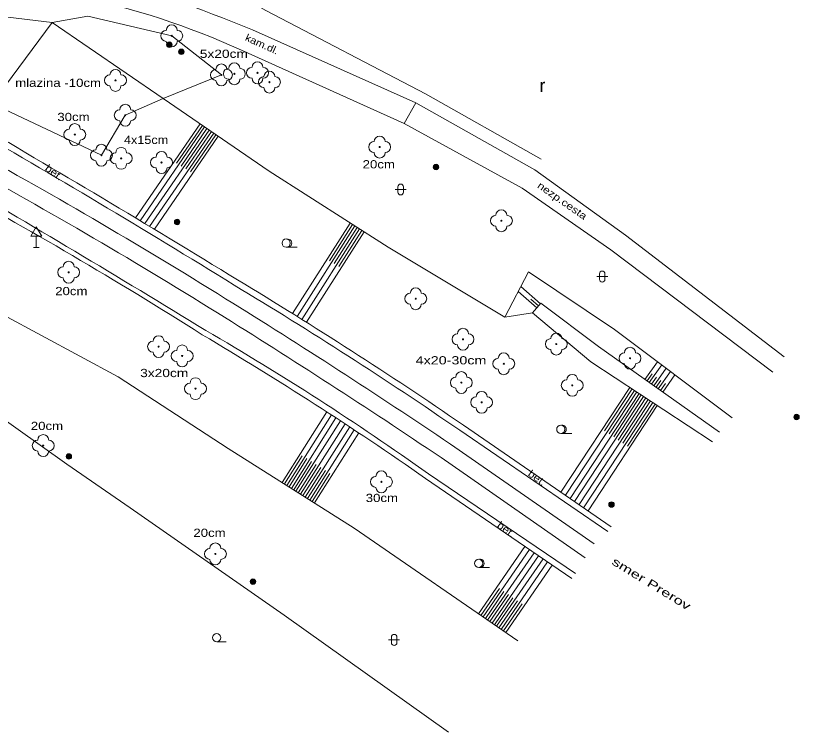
# Model space of a CAD drawing. Extents: x -568501 to -568291, y -1154101 to -1153799.
# Drawn here: x -568402 to -568330.5, y -1153981.7 to -1153916.3 of the extents above; entities that cross this region are included whole.
import ezdxf
from ezdxf.enums import TextEntityAlignment as Align

# ---------------------------------------------------------------- set-up
doc = ezdxf.new("R2010")
doc.units = 0
doc.header["$LTSCALE"] = 0.3
for name, color, linetype, lineweight in [('11', 7, 'Continuous', 13), ('12', 7, 'Continuous', 13), ('14', 7, 'Continuous', 13), ('15', 7, 'Continuous', 13), ('22', 7, 'Continuous', 13), ('23', 7, 'Continuous', 13), ('25', 7, 'Continuous', 13), ('34', 7, 'Continuous', 13), ('36', 7, 'Continuous', 13), ('42', 7, 'Continuous', 13), ('7', 7, 'Continuous', 13)]:
    doc.layers.add(name, color=color, linetype=linetype, lineweight=lineweight)
doc.layers.add('40', color=7, linetype='Continuous')

msp = doc.modelspace()

# ---------------------------------------------------------------- linework, layer by layer
at = {"layer": '11'}
for p, q in [((-568381.39, -1153919.46), (-568366.54, -1153926.14)), ((-568331.89, -1153947.44), (-568346.35, -1153936.33)), ((-568347.69, -1153937.68), (-568332.93, -1153948.84)), ((-568361.48, -1153954.12), (-568347.97, -1153963.37)), ((-568347.67, -1153962.92), (-568361.14, -1153953.66)), ((-568350.92, -1153967.19), (-568364.32, -1153958.11)), ((-568364.59, -1153958.52), (-568351.25, -1153967.65))]:
    msp.add_line(p, q, dxfattribs=at)
for points in [[(-568346.35, -1153936.33), (-568354.63, -1153930.38), (-568365.47, -1153924.26), (-568380.39, -1153917.61)], [(-568365.47, -1153924.26), (-568366.54, -1153926.14), (-568355.77, -1153932.04), (-568347.69, -1153937.68)]]:
    msp.add_lwpolyline(points, dxfattribs=at)
for centre, radius, start, end in [((-568450.7473, -1154089.926), 186.1261, 67.78962, 72.60711), ((-568410.9033, -1153984.3733), 71.3076, 65.55079, 78.28935), ((-569009.5906, -1154964.079), 1200.8724, 58.47781, 59.85365), ((-568847.5367, -1154693.8111), 885.2023, 58.27428, 60.13925), ((-568987.7107, -1154929.3603), 1154.3916, 58.50566, 59.89077), ((-568598.8116, -1154282.7187), 399.3866, 57.62556, 61.60266), ((-568603.2448, -1154307.4258), 428.6782, 55.61365, 58.88779), ((-568594.3404, -1154293.2988), 411.4198, 55.52877, 58.93604), ((-568546.6395, -1154219.0038), 317.7953, 55.0507, 59.41916), ((-568515.3815, -1154170.2907), 260.4616, 54.55112, 59.87018)]:
    msp.add_arc(centre, radius, start, end, dxfattribs=at)
at = {"layer": '12'}
for p, q in [((-568362.31, -1153955.4), (-568349.23, -1153964.49)), ((-568350.03, -1153965.76), (-568363.18, -1153956.62))]:
    msp.add_line(p, q, dxfattribs=at)
for centre, radius, start, end in [((-568635.0051, -1154346.2032), 476.306, 58.03243, 61.43134), ((-568645.0661, -1154364.1594), 495.3805, 58.1384, 61.39848), ((-568708.2241, -1154467.802), 618.2333, 55.97737, 58.24225), ((-568727.54, -1154497.0975), 651.8237, 56.01434, 58.14955)]:
    msp.add_arc(centre, radius, start, end, dxfattribs=at)
at = {"layer": '14'}
msp.add_line((-568398.65, -1153916.93), (-568403.47, -1153916.36), dxfattribs=at)
for points in [[(-568354.85, -1153943.42), (-568357.37, -1153943.81), (-568368.01, -1153937.43), (-568378.86, -1153930.51), (-568388.51, -1153923.88), (-568398.65, -1153916.93)], [(-568415.48, -1153937.58), (-568406.64, -1153941.73), (-568392.63, -1153949.25), (-568382.59, -1153955.78), (-568371.09, -1153963.05), (-568356.19, -1153973.32)], [(-568336.62, -1153953), (-568347.37, -1153944.94), (-568355.21, -1153939.68), (-568357.37, -1153943.81)], [(-568338.42, -1153955.18), (-568349.53, -1153947.88), (-568354.85, -1153943.42), (-568354.07, -1153942.53), (-568348.83, -1153946.49), (-568337.8, -1153954.31)]]:
    msp.add_lwpolyline(points, dxfattribs=at)
at = {"layer": '15'}
for p, q in [((-568385.15, -1153926.188), (-568391.042, -1153934.763)), ((-568384.944, -1153926.33), (-568387.297, -1153929.755)), ((-568384.738, -1153926.471), (-568390.612, -1153935.021)), ((-568384.326, -1153926.754), (-568390.183, -1153935.279)), ((-568383.914, -1153927.038), (-568389.754, -1153935.538)), ((-568384.532, -1153926.613), (-568386.878, -1153930.028)), ((-568384.12, -1153926.896), (-568386.46, -1153930.301)), ((-568383.502, -1153927.321), (-568389.325, -1153935.796)), ((-568383.708, -1153927.179), (-568386.041, -1153930.574)), ((-568371.459, -1153935.23), (-568376.724, -1153943.485)), ((-568371.038, -1153935.499), (-568376.299, -1153943.749)), ((-568371.248, -1153935.365), (-568373.354, -1153938.665)), ((-568370.827, -1153935.633), (-568372.931, -1153938.933)), ((-568370.616, -1153935.768), (-568375.875, -1153944.014)), ((-568370.195, -1153936.037), (-568375.452, -1153944.279)), ((-568370.405, -1153935.902), (-568372.509, -1153939.2)), ((-568354.116, -1153942.582), (-568355.907, -1153941.012)), ((-568354.445, -1153942.958), (-568356.145, -1153941.468)), ((-568354.281, -1153942.77), (-568354.979, -1153942.158)), ((-568344.601, -1153949.488), (-568343.457, -1153947.874)), ((-568344.193, -1153949.777), (-568343.056, -1153948.174)), ((-568343.785, -1153950.067), (-568342.656, -1153948.474)), ((-568344.397, -1153949.633), (-568343.941, -1153948.989)), ((-568343.377, -1153950.356), (-568342.256, -1153948.774)), ((-568342.969, -1153950.645), (-568341.856, -1153949.074)), ((-568343.989, -1153949.922), (-568343.536, -1153949.283)), ((-568343.581, -1153950.211), (-568343.131, -1153949.576)), ((-568343.173, -1153950.5), (-568342.726, -1153949.87)), ((-568345.966, -1153950.222), (-568352.243, -1153959.776)), ((-568345.548, -1153950.496), (-568351.831, -1153960.059)), ((-568345.757, -1153950.359), (-568348.269, -1153954.183)), ((-568345.339, -1153950.634), (-568347.854, -1153954.461)), ((-568345.13, -1153950.771), (-568351.419, -1153960.343)), ((-568344.712, -1153951.046), (-568351.007, -1153960.626)), ((-568344.294, -1153951.32), (-568350.595, -1153960.909)), ((-568344.921, -1153950.908), (-568347.438, -1153954.739)), ((-568344.503, -1153951.183), (-568347.022, -1153955.017)), ((-568343.877, -1153951.595), (-568350.183, -1153961.193)), ((-568343.459, -1153951.869), (-568349.771, -1153961.476)), ((-568344.085, -1153951.457), (-568346.607, -1153955.295)), ((-568343.668, -1153951.732), (-568346.191, -1153955.573)), ((-568377.676, -1153958.886), (-568373.605, -1153952.446)), ((-568377.254, -1153959.153), (-568373.186, -1153952.719)), ((-568376.831, -1153959.421), (-568372.767, -1153952.992)), ((-568376.409, -1153959.688), (-568372.349, -1153953.266)), ((-568375.986, -1153959.955), (-568371.931, -1153953.541)), ((-568375.563, -1153960.222), (-568371.513, -1153953.816)), ((-568375.141, -1153960.489), (-568371.096, -1153954.092)), ((-568374.718, -1153960.756), (-568370.68, -1153954.368)), ((-568377.465, -1153959.02), (-568375.837, -1153956.445)), ((-568377.043, -1153959.287), (-568375.416, -1153956.714)), ((-568376.62, -1153959.554), (-568374.995, -1153956.984)), ((-568376.197, -1153959.821), (-568374.574, -1153957.254)), ((-568375.775, -1153960.088), (-568374.154, -1153957.524)), ((-568375.352, -1153960.356), (-568373.733, -1153957.795)), ((-568374.929, -1153960.623), (-568373.313, -1153958.066)), ((-568359.757, -1153970.861), (-568355.526, -1153964.723)), ((-568359.346, -1153971.145), (-568355.114, -1153965.006)), ((-568358.934, -1153971.429), (-568354.701, -1153965.288)), ((-568358.522, -1153971.713), (-568354.289, -1153965.57)), ((-568358.11, -1153971.996), (-568353.876, -1153965.853)), ((-568357.699, -1153972.28), (-568353.463, -1153966.135)), ((-568357.287, -1153972.564), (-568353.051, -1153966.418)), ((-568359.551, -1153971.003), (-568357.859, -1153968.548)), ((-568359.14, -1153971.287), (-568357.447, -1153968.831)), ((-568358.728, -1153971.571), (-568357.035, -1153969.114)), ((-568358.316, -1153971.854), (-568356.623, -1153969.397)), ((-568357.905, -1153972.138), (-568356.211, -1153969.68)), ((-568357.493, -1153972.422), (-568355.799, -1153969.964))]:
    msp.add_line(p, q, dxfattribs=at)
at = {"layer": '22'}
for centre in [(-568387.74, -1153918.16), (-568383.21, -1153921.72), (-568382.03, -1153921.62), (-568379.92, -1153921.53), (-568392.87, -1153922.22), (-568378.83, -1153922.38), (-568391.98, -1153925.4), (-568396.58, -1153927.16), (-568368.78, -1153928.3), (-568394.15, -1153929.05), (-568392.35, -1153929.33), (-568388.67, -1153929.71), (-568357.68, -1153935.02), (-568397.14, -1153939.72), (-568365.49, -1153942.13), (-568361.18, -1153945.83), (-568352.67, -1153946.27), (-568388.94, -1153946.5), (-568386.79, -1153947.35), (-568345.95, -1153947.56), (-568357.46, -1153948.06), (-568361.33, -1153949.78), (-568385.57, -1153950.33), (-568351.22, -1153950.03), (-568359.48, -1153951.58), (-568399.46, -1153955.52), (-568368.62, -1153958.83), (-568383.76, -1153965.4)]:
    msp.add_circle(centre, 0.05, dxfattribs=at)
for centre, start, end in [((-568388.24, -1153918.16), 90, 270), ((-568387.74, -1153917.66), 0, 180), ((-568387.24, -1153918.16), 270, 90), ((-568387.74, -1153918.66), 180, 0), ((-568382.03, -1153921.12), 0, 180), ((-568379.92, -1153921.03), 0, 180), ((-568392.87, -1153921.72), 0, 180), ((-568383.71, -1153921.72), 90, 270), ((-568383.21, -1153921.22), 0, 180), ((-568382.53, -1153921.62), 90, 270), ((-568382.71, -1153921.72), 270, 90), ((-568381.53, -1153921.62), 270, 90), ((-568380.42, -1153921.53), 90, 270), ((-568379.42, -1153921.53), 270, 90), ((-568393.37, -1153922.22), 90, 270), ((-568392.37, -1153922.22), 270, 90), ((-568379.92, -1153922.03), 180, 0), ((-568379.33, -1153922.38), 90, 270), ((-568378.83, -1153921.88), 0, 180), ((-568378.33, -1153922.38), 270, 90), ((-568392.87, -1153922.72), 180, 0), ((-568383.21, -1153922.22), 180, 0), ((-568382.03, -1153922.12), 180, 0), ((-568378.83, -1153922.88), 180, 0), ((-568392.48, -1153925.4), 90, 270), ((-568391.98, -1153924.9), 0, 180), ((-568391.48, -1153925.4), 270, 90), ((-568396.58, -1153926.66), 0, 180), ((-568391.98, -1153925.9), 180, 0), ((-568397.08, -1153927.16), 90, 270), ((-568396.08, -1153927.16), 270, 90), ((-568396.58, -1153927.66), 180, 0), ((-568368.78, -1153927.8), 0, 180), ((-568394.15, -1153928.55), 0, 180), ((-568392.35, -1153928.83), 0, 180), ((-568369.28, -1153928.3), 90, 270), ((-568368.28, -1153928.3), 270, 90), ((-568394.65, -1153929.05), 90, 270), ((-568393.65, -1153929.05), 270, 90), ((-568392.85, -1153929.33), 90, 270), ((-568391.85, -1153929.33), 270, 90), ((-568389.17, -1153929.71), 90, 270), ((-568388.67, -1153929.21), 0, 180), ((-568388.17, -1153929.71), 270, 90), ((-568368.78, -1153928.8), 180, 0), ((-568394.15, -1153929.55), 180, 0), ((-568392.35, -1153929.83), 180, 0), ((-568388.67, -1153930.21), 180, 0), ((-568357.68, -1153934.52), 0, 180), ((-568358.18, -1153935.02), 90, 270), ((-568357.18, -1153935.02), 270, 90), ((-568357.68, -1153935.52), 180, 0), ((-568397.14, -1153939.22), 0, 180), ((-568397.64, -1153939.72), 90, 270), ((-568396.64, -1153939.72), 270, 90), ((-568397.14, -1153940.22), 180, 0), ((-568365.49, -1153941.63), 0, 180), ((-568365.99, -1153942.13), 90, 270), ((-568364.99, -1153942.13), 270, 90), ((-568365.49, -1153942.63), 180, 0), ((-568361.18, -1153945.33), 0, 180), ((-568388.94, -1153946), 0, 180), ((-568361.68, -1153945.83), 90, 270), ((-568360.68, -1153945.83), 270, 90), ((-568352.67, -1153945.77), 0, 180), ((-568389.44, -1153946.5), 90, 270), ((-568388.44, -1153946.5), 270, 90), ((-568386.79, -1153946.85), 0, 180), ((-568361.18, -1153946.33), 180, 0), ((-568353.17, -1153946.27), 90, 270), ((-568352.17, -1153946.27), 270, 90), ((-568388.94, -1153947), 180, 0), ((-568387.29, -1153947.35), 90, 270), ((-568386.29, -1153947.35), 270, 90), ((-568357.46, -1153947.56), 0, 180), ((-568352.67, -1153946.77), 180, 0), ((-568346.45, -1153947.56), 90, 270), ((-568345.95, -1153947.06), 0, 180), ((-568345.45, -1153947.56), 270, 90), ((-568357.96, -1153948.06), 90, 270), ((-568356.96, -1153948.06), 270, 90), ((-568386.79, -1153947.85), 180, 0), ((-568345.95, -1153948.06), 180, 0), ((-568361.33, -1153949.28), 0, 180), ((-568357.46, -1153948.56), 180, 0), ((-568351.22, -1153949.53), 0, 180), ((-568386.07, -1153950.33), 90, 270), ((-568385.57, -1153949.83), 0, 180), ((-568385.07, -1153950.33), 270, 90), ((-568361.83, -1153949.78), 90, 270), ((-568360.83, -1153949.78), 270, 90), ((-568351.72, -1153950.03), 90, 270), ((-568350.72, -1153950.03), 270, 90), ((-568361.33, -1153950.28), 180, 0), ((-568359.48, -1153951.08), 0, 180), ((-568351.22, -1153950.53), 180, 0), ((-568385.57, -1153950.83), 180, 0), ((-568359.98, -1153951.58), 90, 270), ((-568358.98, -1153951.58), 270, 90), ((-568359.48, -1153952.08), 180, 0), ((-568399.46, -1153955.02), 0, 180), ((-568399.96, -1153955.52), 90, 270), ((-568398.96, -1153955.52), 270, 90), ((-568399.46, -1153956.02), 180, 0), ((-568369.12, -1153958.83), 90, 270), ((-568368.62, -1153958.33), 0, 180), ((-568368.12, -1153958.83), 270, 90), ((-568368.62, -1153959.33), 180, 0), ((-568384.26, -1153965.4), 90, 270), ((-568383.76, -1153964.9), 0, 180), ((-568383.26, -1153965.4), 270, 90), ((-568383.76, -1153965.9), 180, 0)]:
    msp.add_arc(centre, 0.5, start, end, dxfattribs=at)
at = {"layer": '23'}
for points in [[(-568354.04, -1153929.41), (-568364.61, -1153923.44), (-568379.16, -1153915.86), (-568390.37, -1153909.46), (-568387.81, -1153906.15), (-568381.36, -1153897.16), (-568374.28, -1153888.42), (-568365.82, -1153877.84), (-568356.68, -1153865.62), (-568346.38, -1153852.31), (-568338.19, -1153841.21)], [(-568398.65, -1153916.93), (-568404.16, -1153924.33), (-568394.15, -1153929.05)], [(-568398.65, -1153916.93), (-568395.38, -1153916.38), (-568387.74, -1153918.16), (-568383.21, -1153921.72), (-568388.51, -1153923.88)], [(-568394.15, -1153929.05), (-568391.98, -1153925.4), (-568388.51, -1153923.88)]]:
    msp.add_lwpolyline(points, dxfattribs=at)
at = {"layer": '25'}
for centre, radius in [((-568387.96, -1153918.97), 0.25), ((-568387.96, -1153918.97), 0.2), ((-568387.96, -1153918.97), 0.15), ((-568387.96, -1153918.97), 0.1), ((-568387.96, -1153918.97), 0.05), ((-568386.87, -1153919.61), 0.25), ((-568386.87, -1153919.61), 0.2), ((-568386.87, -1153919.61), 0.15), ((-568386.87, -1153919.61), 0.1), ((-568386.87, -1153919.61), 0.05), ((-568363.64, -1153930.12), 0.25), ((-568363.64, -1153930.12), 0.2), ((-568363.64, -1153930.12), 0.15), ((-568363.64, -1153930.12), 0.1), ((-568363.64, -1153930.12), 0.05), ((-568387.25, -1153935.13), 0.25), ((-568387.25, -1153935.13), 0.2), ((-568387.25, -1153935.13), 0.15), ((-568387.25, -1153935.13), 0.1), ((-568387.25, -1153935.13), 0.05), ((-568330.76, -1153952.92), 0.25), ((-568330.76, -1153952.92), 0.2), ((-568330.76, -1153952.92), 0.15), ((-568330.76, -1153952.92), 0.1), ((-568330.76, -1153952.92), 0.05), ((-568397.12, -1153956.51), 0.25), ((-568397.12, -1153956.51), 0.2), ((-568397.12, -1153956.51), 0.15), ((-568397.12, -1153956.51), 0.1), ((-568397.12, -1153956.51), 0.05), ((-568347.64, -1153960.9), 0.25), ((-568347.64, -1153960.9), 0.2), ((-568347.64, -1153960.9), 0.15), ((-568347.64, -1153960.9), 0.1), ((-568347.64, -1153960.9), 0.05), ((-568380.33, -1153967.93), 0.25), ((-568380.33, -1153967.93), 0.2), ((-568380.33, -1153967.93), 0.15), ((-568380.33, -1153967.93), 0.1), ((-568380.33, -1153967.93), 0.05)]:
    msp.add_circle(centre, radius, dxfattribs=at)
at = {"layer": '34'}
for p, q in [((-568400.09, -1153936.432), (-568400.09, -1153937.45)), ((-568400.34, -1153937.45), (-568399.84, -1153937.45))]:
    msp.add_line(p, q, dxfattribs=at)
msp.add_lwpolyline([(-568400.59, -1153936.432), (-568399.59, -1153936.432), (-568400.09, -1153935.566)], close=True, dxfattribs=at)
at = {"layer": '36'}
for p, q in [((-568367.112, -1153931.92), (-568367.112, -1153932.42)), ((-568366.612, -1153931.92), (-568366.612, -1153932.42)), ((-568367.362, -1153932.17), (-568366.362, -1153932.17)), ((-568377.303, -1153937.435), (-568376.303, -1153937.435)), ((-568348.735, -1153939.858), (-568348.735, -1153940.358)), ((-568348.235, -1153939.858), (-568348.235, -1153940.358)), ((-568348.985, -1153940.108), (-568347.985, -1153940.108)), ((-568352.263, -1153954.415), (-568351.263, -1153954.415)), ((-568359.75, -1153966.636), (-568358.75, -1153966.636)), ((-568383.639, -1153973.411), (-568382.764, -1153973.411)), ((-568367.958, -1153973.24), (-568366.958, -1153973.24)), ((-568367.708, -1153972.99), (-568367.708, -1153973.49)), ((-568367.208, -1153972.99), (-568367.208, -1153973.49))]:
    msp.add_line(p, q, dxfattribs=at)
for centre in [(-568377.3024, -1153937.0594), (-568352.2624, -1153954.039), (-568359.7499, -1153966.2605), (-568383.6392, -1153973.0356)]:
    msp.add_circle(centre, 0.375, dxfattribs=at)
for centre, radius, start, end in [((-568366.8622, -1153931.921), 0.25, 0, 180), ((-568366.8622, -1153932.421), 0.25, 180, 0), ((-568377.1774, -1153937.0594), 0.375, 260.40593, 99.59407), ((-568348.4848, -1153939.8588), 0.25, 0, 180), ((-568348.4848, -1153940.3588), 0.25, 180, 0), ((-568352.1374, -1153954.039), 0.375, 260.40593, 99.59407), ((-568359.6249, -1153966.2605), 0.375, 260.40593, 99.59407), ((-568367.4571, -1153972.991), 0.25, 0, 180), ((-568367.4571, -1153973.491), 0.25, 180, 0)]:
    msp.add_arc(centre, radius, start, end, dxfattribs=at)
at = {"layer": '7'}
for points in [[(-568418.88, -1153947.23), (-568416.54, -1153943.33), (-568413.3, -1153945.67), (-568409.87, -1153948.17), (-568406.63, -1153950.58), (-568397.3, -1153957.22)], [(-568397.3, -1153957.22), (-568391.53, -1153961.19), (-568377.5, -1153970.99), (-568362.5, -1153981.67)]]:
    msp.add_lwpolyline(points, dxfattribs=at)

# ---------------------------------------------------------------- texts
at = {"layer": '36'}
msp.add_text('r', height=1.2, dxfattribs=at).set_placement((-568353.9335, -1153923.281), align=Align.CENTER)
at = {"layer": '40'}
for s, rotation, width, p in [('kam.dl.', 335.605, 1.15, (-568381.11, -1153918.552)), ('bet.', 323.922, 1.2, (-568399.356, -1153930.362)), ('nezp.cesta', 325.064, 1.25, (-568354.467, -1153931.957)), ('bet.', 323.922, 1.2, (-568355.318, -1153958.219)), ('bet.', 323.922, 1.2, (-568358.138, -1153962.914))]:
    msp.add_text(s, height=0.65, rotation=rotation, dxfattribs=dict(at, width=width)).set_placement(p)
at = {"layer": '42'}
for s, width, p in [('5x20cm', 1.25, (-568382.9875, -1153920.17)), ('mlazina -10cm', 1.2, (-568398.1005, -1153922.818)), ('30cm', 1.2, (-568396.7005, -1153925.928)), ('4x15cm', 1.15, (-568390.08, -1153928.019)), ('20cm', 1.2, (-568368.8595, -1153930.247)), ('20cm', 1.2, (-568396.8955, -1153941.807)), ('4x20-30cm', 1.3, (-568362.271, -1153948.12)), ('3x20cm', 1.25, (-568388.4255, -1153949.279)), ('20cm', 1.2, (-568399.1185, -1153954.101)), ('30cm', 1.2, (-568368.5785, -1153960.669)), ('20cm', 1.2, (-568384.2955, -1153963.851))]:
    msp.add_text(s, height=0.75, dxfattribs=dict(at, width=width)).set_placement(p, align=Align.CENTER)
at = {"layer": '42', "width": 1.5}
msp.add_text('smer Prerov', height=0.75, rotation=328.512, dxfattribs=at).set_placement((-568344.1979, -1153968.4377), align=Align.CENTER)

doc.saveas('drawing.dxf')
